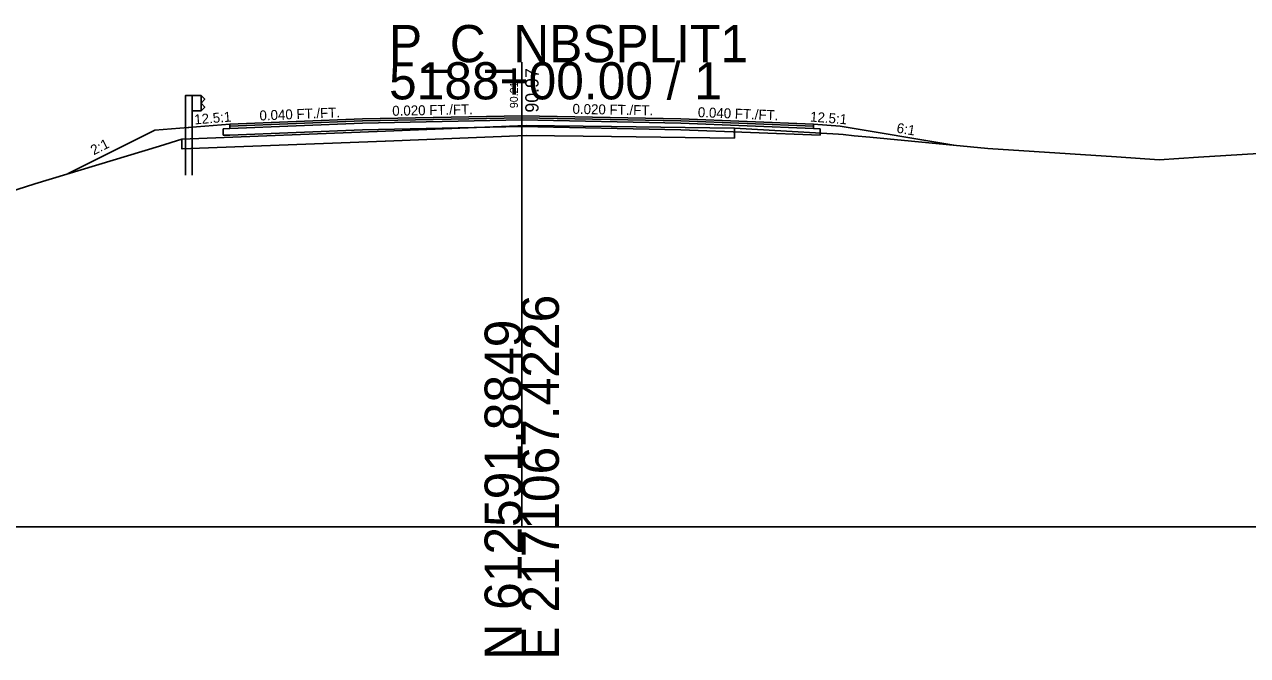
# Model space of a CAD drawing. Extents: x -26 to 1303, y -3010 to 12038.
# Drawn here: x 112.5 to 204.7, y 7490.3 to 7537.8 of the extents above; entities that cross this region are included whole.
import ezdxf

# ---------------------------------------------------------------- set-up
doc = ezdxf.new("R2010")
doc.units = 0
for name, color, linetype in [('RD_GPK_XS_Cell', 7, 'Continuous'), ('RD_PD_Final_TrvlWay', 7, 'Continuous'), ('RD_XS_Base', 7, 'Continuous'), ('RD_XS_ExGround', 7, 'Continuous'), ('RD_XS_ExPaveRet', 7, 'Continuous'), ('RD_XS_GR', 7, 'Continuous'), ('RD_XS_Greenside', 7, 'Continuous'), ('RD_XS_Pave', 7, 'Continuous'), ('RD_XS_PaveOvlay_CP', 7, 'Continuous'), ('RD_XS_TieSlope', 7, 'Continuous'), ('RD_XS_TX_Elev_EX', 7, 'Continuous'), ('RD_XS_TX_Elev_PR', 7, 'Continuous'), ('RD_XS_TX_ShdSlope', 7, 'Continuous'), ('RD_XS_TX_Slope', 7, 'Continuous')]:
    doc.layers.add(name, color=color, linetype=linetype)

msp = doc.modelspace()

# ---------------------------------------------------------------- linework, layer by layer
at = {"layer": 'RD_GPK_XS_Cell'}
for p, q in [((150, 7500), (150, 7535)), ((0, 7500), (150, 7500)), ((150, 7500), (300, 7500))]:
    msp.add_line(p, q, dxfattribs=at)
at = {"layer": 'RD_PD_Final_TrvlWay'}
for p, q in [((125.167, 7530.104), (124.667, 7530.064)), ((124.667, 7530.064), (124.667, 7526.499)), ((125.167, 7526.499), (125.167, 7530.104))]:
    msp.add_line(p, q, dxfattribs=at)
at = {"layer": 'RD_XS_Base'}
for p, q in [((138, 7530.413), (128, 7530.013)), ((150, 7530.653), (138, 7530.413)), ((138, 7530.413), (138, 7530.413)), ((150, 7530.653), (150, 7530.812)), ((150, 7530.812), (150, 7530.812)), ((150, 7530.812), (150, 7530.812)), ((150, 7530.812), (150, 7530.153)), ((150, 7530.153), (150, 7530.653)), ((150, 7530.653), (150, 7530.653)), ((150, 7530.653), (150, 7530.653)), ((150, 7530.653), (150, 7530.653)), ((162, 7530.413), (150, 7530.653)), ((172, 7530.013), (162, 7530.413)), ((128, 7530.013), (127.5, 7529.993)), ((127.5, 7529.993), (127.5, 7529.993)), ((127.5, 7529.993), (127.5, 7529.493)), ((127.5, 7529.493), (128, 7529.513)), ((128, 7530.013), (128, 7530.013)), ((128, 7529.513), (138, 7529.913)), ((128, 7529.513), (128, 7529.513)), ((138, 7529.913), (150, 7530.153)), ((138, 7529.913), (138, 7529.913)), ((150, 7530.153), (150, 7530.153)), ((150, 7530.153), (150, 7530.153)), ((150, 7530.153), (162, 7529.913)), ((162, 7529.913), (172.5, 7529.493)), ((164, 7530.333), (164, 7530.333)), ((164, 7529.833), (164, 7529.833)), ((172.5, 7529.993), (172, 7530.013)), ((172, 7530.013), (172, 7530.013)), ((172.5, 7529.493), (172.5, 7529.993)), ((172.5, 7529.993), (172.5, 7529.993))]:
    msp.add_line(p, q, dxfattribs=at)
at = {"layer": 'RD_XS_ExGround'}
msp.add_lwpolyline([(109.432, 7524.614), (113.291, 7525.849), (122.705, 7528.676), (124.394, 7529.212), (139.729, 7529.81), (150.346, 7530.226), (156.761, 7530.145), (166.025, 7530.034), (173.871, 7529.571), (174.215, 7529.554), (175.062, 7529.449), (176.227, 7529.343), (185.139, 7528.499), (194.825, 7527.878), (198.047, 7527.656), (201, 7527.837), (211.71, 7528.496)], dxfattribs=at)
at = {"layer": 'RD_XS_ExPaveRet'}
for p, q in [((139.729, 7529.81), (124.394, 7529.212)), ((150.346, 7530.226), (139.729, 7529.81)), ((156.761, 7530.145), (150.346, 7530.226)), ((166.025, 7530.034), (156.761, 7530.145))]:
    msp.add_line(p, q, dxfattribs=at)
for points in [[(166.025, 7530.034), (156.761, 7530.145), (156.761, 7530.145), (150.346, 7530.226), (139.729, 7529.81), (139.729, 7529.81), (124.394, 7529.212), (124.394, 7529.212), (124.394, 7529.212), (124.394, 7528.462), (124.394, 7528.462), (139.729, 7529.06), (139.729, 7529.06), (150.346, 7529.476), (156.761, 7529.395), (156.761, 7529.395), (166.025, 7529.284), (166.025, 7529.284), (166.025, 7530.034), (166.025, 7530.034), (166.025, 7530.034)], [(124.394, 7529.212), (124.394, 7528.462), (139.729, 7529.06), (150.346, 7529.476), (156.761, 7529.395), (166.025, 7529.284), (166.025, 7530.034)]]:
    msp.add_lwpolyline(points, dxfattribs=at)
at = {"layer": 'RD_XS_GR'}
for points in [[(125.167, 7532.499), (125.167, 7530.104), (124.667, 7530.064), (124.667, 7532.499), (124.917, 7532.499), (125.167, 7532.499)], [(125.834, 7532.499), (125.834, 7531.332), (125.167, 7531.332), (125.167, 7532.499), (125.834, 7532.499)], [(125.834, 7532.499), (125.834, 7532.499), (125.834, 7532.499), (125.834, 7531.332), (126.105, 7531.624), (126.105, 7531.624), (125.834, 7531.916), (125.834, 7531.916), (126.105, 7532.207), (126.105, 7532.207), (125.834, 7532.499)]]:
    msp.add_lwpolyline(points, dxfattribs=at)
at = {"layer": 'RD_XS_Greenside'}
for p, q in [((122.355, 7529.879), (115.806, 7526.605)), ((174, 7530.171), (182.566, 7528.743))]:
    msp.add_line(p, q, dxfattribs=at)
at = {"layer": 'RD_XS_Pave'}
for p, q in [((138, 7530.731), (128, 7530.331)), ((138, 7530.572), (128, 7530.172)), ((128, 7530.172), (138, 7530.572)), ((128, 7530.013), (138, 7530.413)), ((150, 7530.971), (138, 7530.731)), ((150, 7530.812), (138, 7530.572)), ((138, 7530.572), (150, 7530.812)), ((138, 7530.731), (138, 7530.731)), ((138, 7530.413), (150, 7530.653)), ((138, 7530.572), (138, 7530.572)), ((138, 7530.572), (138, 7530.572)), ((138, 7530.413), (138, 7530.413)), ((162, 7530.731), (150, 7530.971)), ((150, 7530.971), (150, 7530.971)), ((150, 7530.971), (150, 7530.971)), ((150, 7530.653), (150, 7530.812)), ((150, 7530.812), (150, 7530.812)), ((150, 7530.812), (150, 7530.812)), ((150, 7530.812), (150, 7530.812)), ((150, 7530.812), (150, 7530.812)), ((150, 7530.812), (162, 7530.572)), ((162, 7530.572), (150, 7530.812)), ((150, 7530.812), (150, 7530.812)), ((150, 7530.812), (150, 7530.812)), ((150, 7530.812), (150, 7530.653)), ((150, 7530.653), (150, 7530.653)), ((150, 7530.653), (150, 7530.653)), ((150, 7530.653), (162, 7530.413)), ((172, 7530.331), (162, 7530.731)), ((162, 7530.572), (172, 7530.172)), ((172, 7530.172), (162, 7530.572)), ((162, 7530.413), (172, 7530.013)), ((164, 7530.651), (164, 7530.651)), ((164, 7530.492), (164, 7530.492)), ((164, 7530.492), (164, 7530.492)), ((128, 7530.331), (128, 7530.331)), ((128, 7530.331), (128, 7530.172)), ((128, 7530.172), (128, 7530.172)), ((128, 7530.172), (128, 7530.013)), ((164, 7530.333), (164, 7530.333)), ((172, 7530.172), (172, 7530.331)), ((172, 7530.331), (172, 7530.331)), ((172, 7530.013), (172, 7530.172)), ((172, 7530.172), (172, 7530.172))]:
    msp.add_line(p, q, dxfattribs=at)
at = {"layer": 'RD_XS_PaveOvlay_CP'}
for p, q in [((128, 7530.331), (138, 7530.731)), ((138, 7530.731), (150, 7530.971)), ((150, 7530.971), (162, 7530.731)), ((162, 7530.731), (172, 7530.331))]:
    msp.add_line(p, q, dxfattribs=at)
at = {"layer": 'RD_XS_TieSlope'}
for p, q in [((128, 7530.331), (122.355, 7529.879)), ((172, 7530.331), (174, 7530.171))]:
    msp.add_line(p, q, dxfattribs=at)

# ---------------------------------------------------------------- texts
at = {"layer": 'RD_GPK_XS_Cell'}
for s, p in [('P_C_NBSPLIT1', (140, 7535)), ('5188+00.00 / 1', (140, 7532.2))]:
    msp.add_text(s, height=2.8, dxfattribs=at).set_placement(p)
for s, p in [('E 2171067.4226', (152.8, 7490)), ('N 612591.8849', (150, 7490))]:
    msp.add_text(s, height=2.8, rotation=90, dxfattribs=at).set_placement(p)
at = {"layer": 'RD_XS_TX_Elev_EX'}
msp.add_text('90.21', height=0.6, rotation=90, dxfattribs=at).set_placement((149.709, 7531.536))
at = {"layer": 'RD_XS_TX_Elev_PR'}
msp.add_text('90.97', height=1, rotation=90, dxfattribs=at).set_placement((151.267, 7531.205))
at = {"layer": 'RD_XS_TX_ShdSlope'}
for rotation, p in [(4.57392, (125.35, 7530.31)), (355.42608, (171.711, 7530.536))]:
    msp.add_text('12.5:1', height=0.75, rotation=rotation, dxfattribs=at).set_placement(p)
at = {"layer": 'RD_XS_TX_Slope'}
for s, rotation, p in [('0.040 FT./FT.', 2.29061, (130.247, 7530.606)), ('0.020 FT./FT.', 1.14576, (140.248, 7530.961)), ('0.020 FT./FT.', 358.85424, (153.822, 7531.114)), ('0.040 FT./FT.', 357.70939, (163.262, 7530.866)), ('6:1', 350.53768, (178.215, 7529.701)), ('2:1', 26.56505, (117.736, 7527.979))]:
    msp.add_text(s, height=0.75, rotation=rotation, dxfattribs=at).set_placement(p)

doc.saveas('drawing.dxf')
